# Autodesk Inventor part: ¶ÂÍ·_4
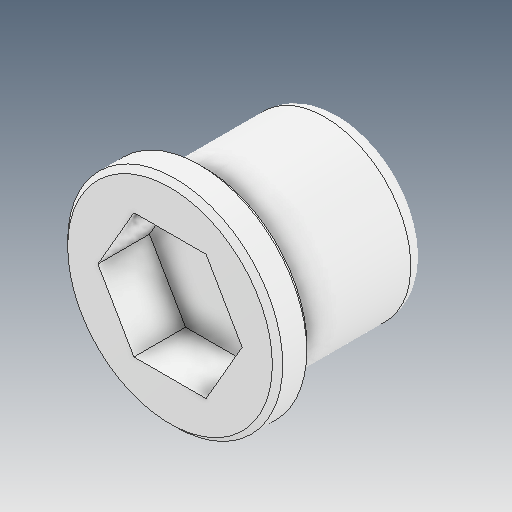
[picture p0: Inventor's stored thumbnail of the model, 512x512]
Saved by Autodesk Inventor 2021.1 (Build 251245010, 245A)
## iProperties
Created: 2021-06
Part Number: ¶ÂÍ·_4
Material: Ogólny
Document SubType Name: Modeling
Designer: user
Density: 1 g/cm^3
Appearance: Domyślna
Author: user
Revision Number: ÈÎºÎ
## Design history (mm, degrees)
feature "ÊäÈë1"
node "Bryła1"
